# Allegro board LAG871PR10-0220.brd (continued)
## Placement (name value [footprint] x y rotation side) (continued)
CZ234  100P_0201_25V8J  [C_0201]  303.79 98.06 180 top
CZ303  0.1U_0201_10V6K  [C_0201]  146.41 50.26 180 top
CZ305  0.1U_0201_10V6K  [C_0201]  23.09 32.63 180 top
CZ306  470P_0402_50V7K  [C_0402]  23.29 33.9 180 top
CZ307  27P_0201_25V8  [C_0201]  303.76 95.87 270 top
CZ308  27P_0201_25V8  [C_0201]  303.79 98.63 180 top
CZ309  0.1U_0201_10V6K  [C_0201]  308.29 97.73 0 bottom
CZ311  27P_0402_50V8J  [C_0402]  269.33 63.91 90 top
CZ312  27P_0402_50V8J  [C_0402]  268.42 63.91 90 top
DA1  AZ5123-02S.R7G_SOT23-3  [L03ESDL5V0CC3-2_SOT23-3]  299.28 33.75 180 bottom
DA2  AZ5125-02S.R7G_SOT23-3  [AZ5125-02SPR7G_SOT23-3]  299.92 47.71 0 bottom
DA3  AZ5123-02S.R7G_SOT23-3  [L03ESDL5V0CC3-2_SOT23-3]  304.93 47.9 0 bottom
DA6  -  [L03ESDL5V0CG3-2_SOT-523-3]  302.33 20.06 180 bottom
DA7  -  [L03ESDL5V0CG3-2_SOT-523-3]  298.01 20.06 180 bottom
DA8  -  [RB751S-40_SOD523-2]  272.48 47.63 270 top
DC1  -  [RB751S-40_SOD523-2]  173.42 56.32 0 top
DC2  -  [RB751S-40_SOD523-2]  175.12 55.11 180 top
DC4  -  [RB521CM-30T2R_SOD923-2]  174.89 74.51 270 bottom
DD1  -  [CEST523NC5VB_SOT-523-3]  142.95 27.78 270 top
DE1  BZV55-B5V6_SOD80C2  [BZV55-B5V1_SOD80C2]  187.75 83.05 270 bottom
DE2  -  [RB751S-40_SOD523-2]  278.24 64.22 90 top
DI1  -  [AZ1045-04F_DFN2510P10E-10-9]  23.64 40.26 90 top
DI2  -  [CEST523NC5VB_SOT-523-3]  23.5 37.4 90 bottom
DI4  -  [AZ1045-04F_DFN2510P10E-10-9]  294.42 83.28 270 top
DI5  -  [CEST523NC5VB_SOT-523-3]  294.78 87.5 90 top
DT1  1N4148WS-L_SOD323-2  [1N4148WS-7-F_SOD323-2]  26 88.89 180 top
DT2  1N4148WS-L_SOD323-2  [1N4148WS-7-F_SOD323-2]  23.25 34.51 180 bottom
DT3  1N4148WS-L_SOD323-2  [1N4148WS-7-F_SOD323-2]  20.54 32.04 0 bottom
DT4  AZ4A24-01F.R7G_DFN0603P2Y2  [AZ4A24-01FPR7G_DFN0603P2Y2]  11.69 93.58 90 bottom
DT5  DESD3V3Z1BCSF-7 X2-DSN0603-2  [ESD8011MUT5G_X3DFN2-2]  13.91 81.81 270 bottom
DT6  DESD3V3Z1BCSF-7 X2-DSN0603-2  [ESD8011MUT5G_X3DFN2-2]  13.91 82.52 90 bottom
DT9  DESD3V3Z1BCSF-7 X2-DSN0603-2  [ESD8011MUT5G_X3DFN2-2]  13.15 89.72 90 bottom
DT10  DESD3V3Z1BCSF-7 X2-DSN0603-2  [ESD8011MUT5G_X3DFN2-2]  13.15 89.01 270 bottom
DT13  DESD3V3Z1BCSF-7 X2-DSN0603-2  [ESD8011MUT5G_X3DFN2-2]  13.91 81.81 270 top
DT14  DESD3V3Z1BCSF-7 X2-DSN0603-2  [ESD8011MUT5G_X3DFN2-2]  13.91 82.52 90 top
DT17  DESD3V3Z1BCSF-7 X2-DSN0603-2  [ESD8011MUT5G_X3DFN2-2]  13.15 89.72 90 top
DT18  DESD3V3Z1BCSF-7 X2-DSN0603-2  [ESD8011MUT5G_X3DFN2-2]  13.15 89.01 270 top
DT39  AZ1045-04F_DFN2510P10E-10-9  [L05ESDL5V0NA-4_SLP2510P8-10-9]  13.2 86.89 90 bottom
DT40  AZ1045-04F_DFN2510P10E-10-9  [L05ESDL5V0NA-4_SLP2510P8-10-9]  13.2 84.89 270 top
DV1  -  [BAT54CW_SOT323-3]  68.55 105.15 90 top
DV2  -  [BAT54CW_SOT323-3]  48.14 106.74 270 top
DV3  BAT54CTB_SOT-523  [BAT54CT-7-F_SOT523-3]  103.32 95.24 270 bottom
DV11  -  [RB751S-40_SOD523-2]  69.65 102.69 270 top
DV12  -  [RB751S-40_SOD523-2]  87.66 104.58 180 top
DV13  -  [CEST523NC5VB_SOT-523-3]  57.79 107.37 180 top
DV14  -  [CEST523NC5VB_SOT-523-3]  61.6 107.37 180 top
DZ1  -  [RB751S-40_SOD523-2]  273.65 50.92 180 top
DZ2  -  [RB751S-40_SOD523-2]  273.65 49.59 180 top
DZ5  -  [RB751S-40_SOD523-2]  273.01 60.35 90 top
DZ6  -  [RB751S-40_SOD523-2]  274.28 60.35 90 top
DZ8  -  [RB751S-40_SOD523-2]  277.95 30.18 270 bottom
DZ9  BAT54CTB_SOT-523-3  [BAT54CT-7-F_SOT523-3]  253.2 39.08 90 bottom
DZ10  -  [CEST523NC5VB_SOT-523-3]  91.89 107.94 180 top
DZ11  -  [CEST523NC5VB_SOT-523-3]  314.18 95.53 0 bottom
DZ12  -  [RB751S-40_SOD523-2]  300.69 6.14 90 top
DZ13  -  [AZ1045-04F_DFN2510P10E-10-9]  296.18 55.5 90 top
DZ14  -  [AZ1045-04F_DFN2510P10E-10-9]  310.69 96.66 0 bottom
DZ15  -  [AZ1045-04F_DFN2510P10E-10-9]  307.59 96.67 0 bottom
DZ21  -  [CEST523NC5VB_SOT-523-3]  96.84 107.94 180 top
FD1  FIDUCIAL MARK~D  [FIDUCIAL_C40M80]  10.42 20.31 0 top
FD2  FIDUCIAL MARK~D  [FIDUCIAL_C40M80]  268.64 107.74 0 top
FD3  FIDUCIAL MARK~D  [FIDUCIAL_C40M80]  10.55 20.06 180 bottom
FD4  FIDUCIAL MARK~D  [FIDUCIAL_C40M80]  270.27 104.71 180 bottom
FV1  1A_65V_T0603FF1000TM  [F_T0603FF1000TM]  91.21 101.21 180 bottom
FV2  0.5A_65V_T0603FF0500TM  [F_T0603FF0500TM]  77.31 110.04 0 top
FZ1  0.5A_65V_T0603FF0500TM  [F_T0603FF0500TM]  54.51 107.18 90 top
FZ2  1A_65V_T0603FF1000TM  [F_T0603FF1000TM]  104.3 106.47 90 top
H1  -  [H_3P7]  163.83 90.45 180 bottom
H2  -  [H_3P7]  163.83 69.25 180 bottom
H3  -  [H_3P7]  99.43 69.25 180 bottom
H4  -  [H_3P7]  99.43 90.45 180 bottom
H5  H_4P0  [H_4P0-G]  158.73 101.57 180 bottom
H8  H_4P0  [H_4P0-G]  158.73 25.15 180 bottom
H11  H_2P6  [H_2P6-G]  5.73 94.3 180 bottom
H12  H_2P6  [H_2P6-G]  4.43 77.85 180 bottom
H13  H_3P1  [H_3P1-G]  4.78 23.65 180 bottom
H14  H_2P3  [H_2P3-G]  49.23 111.95 180 bottom
H15  H_2P6  [H_2P6-G]  264.73 111.55 180 bottom
H16  H_2P6  [H_2P6-G]  301.59 102.45 180 bottom
H17  H_2P6  [H_2P6-G]  313.5 70.85 180 bottom
H18  H_3P1  [H_3P1-G]  312.68 23.65 180 bottom
H20  -  [H_3P2]  290.58 45.13 180 bottom
H21  -  [H_3P2]  276.44 102.35 180 bottom
H27  H_3P6X2P6  [H_3P6X2P6-G]  4.78 28.95 180 bottom
H28  H_2P6  [H_2P6-G]  312.68 28.95 180 bottom
H29  -  [H_0P6X2P8]  304.94 102.45 0 top
H30  -  [H_2P5X0P7]  8.39 94.3 90 top
H31  -  [H_2P5X0P7]  7.08 77.85 90 top
JANT1  I-PEX_20854-005E-00  [I-PEX_20854-005E-00_5P-T]  306.02 107.95 270 bottom
JANT2  I-PEX_20854-005E-00  [I-PEX_20854-005E-00_5P-T]  306.02 98.35 270 bottom
JAPS1  CVILU_CF4218FH0R0-05-NH  [CVILU_CF4218FH0R0-05-NH_18P-T]  298.45 31.03 180 bottom
JASA1  CVILU_CI1804M1HRG-NH  [CVILU_CI1804M1HRG-NH_4P]  106.93 112.05 180 bottom
JDEG1  JXT_FP241AH-010GAAM  [JXT_FP241AH-010GAAM_10P]  295.86 87.59 90 bottom
JDIMM1  LOTES_ADDR0206-P001A  [FOX_ASAA821-H4RB5-7H_260P]  57.46 39.23 180 bottom
JDIMM2  LOTES_ADDR0206-P001A  [FOX_ASAA821-H4RB5-7H_260P]  134.66 39.23 180 bottom
JEDP1  I-PEX_20879-040E-01  [I-PEX_20879-040E-01_40P-T]  57.43 111.32 180 bottom
JESPI  JXT_FP241AH-010GAAM  [JXT_FP241AH-010GAAM_10P]  295.92 78.63 90 bottom
JFAN1  ACES_50271-0040N-001  [ACES_50271-0040N-001_4P]  191.31 79.4 270 bottom
JFPBTN1  FOX_QT510166-L010-7H  [FOX_QT510166-L010-7H_16P]  307.8 100.8 270 bottom
JHDMI1  ACON_HMRBL-A41L0F  [ACON_HMRBL-A41L0F_19P-T]  11.6 60.25 90 bottom
JHP1  SINGA_2SJ3095-085111F  [SINGA_2SJ3095-085111F_6P]  304.51 42.95 90 bottom
JIRTS1  ACES_50208-0180N-P01  [ACES_50208-0180N-P01_18P-T-S]  88.32 112.05 180 bottom
JKBTP1  HRS_TF31-20S-0P5SH-800  [HRS_TF31-20S-0P5SH-800_20P-T]  245.08 32.55 0 bottom
JLED1  HRS_TF31-4S-0P5SH-800  [HRS_TF31-4S-0P5SH-800_4P-T]  309.08 6.95 0 bottom
JNGFF1  LOTES_APCI0128-P005A  [LOTES_APCI0128-P005A_75P]  257.05 54.38 270 bottom
JNGFF2  DEREN_40-42313-06711RHFAN  [ACES_40-42313-06711RHFAN_75P-T]  267.18 56.82 0 bottom
JNGFF3  LOTES_APCI0170-P001A  [LOTES_APCI0170-P001A_75P]  33.88 22.6 180 bottom
JRTC1  ACES_50271-0020N-001  [ACES_50271-0020N-001_2P]  290.34 15.26 270 bottom
JSD1  T-SOL_158-1240902600  [T-SOL_158-1240902600_23P-T]  302.95 61.03 90 top
JSIM1  TAISO_159-1000300600  [TAISO_159-1000300600_8P-T]  301.47 63.01 270 bottom
JSPI1  ACES_50506-02041-P01  [ACES_50506-02041-P01_20P]  184.6 72.01 180 bottom
JSPK1  ACES_50278-00801-001  [ACES_50278-00801-001_8P]  292.64 8.1 180 bottom
JTAG1  @SHORT PADS~D  [SHORTPADS]  273.56 96.26 180 top
JUSB1  ACON_TCRA2-9U1U93  [ACON_TCRA2-9U1U93_9P-T]  301.11 79.73 270 bottom
JUSB2  ACON_TCRA2-9U1U93  [ACON_TCRA2-9U1U93_9P-T]  16.36 45.25 90 bottom
JUSBC1  JAE_DX07SD24JJ2R1300~D  [JAE_DX07SD24JJ2R1300_24P]  7.55 88.47 270 top
JUSH1  HRS_TF31C-26S-0P5SH-800  [HRS_TF31C-26S-0P5SH-800_26P-T]  261.43 32.55 0 bottom
JXDP1  JXT_FP270H-061G1AM  [JXT_FP270H-061G1AM_61P]  73.88 96.5 180 bottom
LA5  BLM15PX600SN1D_2P  [MURAT_BLM15PX600SN1D_2P]  283.28 47.38 90 top
LA6  BLM15PD800SN1D_2P  [MURAT_BLM15PD800SN1D_2P]  303.87 20.47 270 bottom
LA7  BLM15PD800SN1D_2P  [MURAT_BLM15PD800SN1D_2P]  300.81 20.61 270 bottom
LA8  BLM15PD800SN1D_2P  [MURAT_BLM15PD800SN1D_2P]  299.54 20.36 270 bottom
LA9  BLM15PD800SN1D_2P  [MURAT_BLM15PD800SN1D_2P]  296.51 20.6 270 bottom
LA10  BLM15PX330SN1D_2P  [MURAT_BLM15PX330SN1D_2P]  299.36 45.52 0 top
LA11  BLM15PX330SN1D_2P  [MURAT_BLM15PX330SN1D_2P]  304.7 46.22 0 top
LA12  BLM15PX600SN1D_2P  [MURAT_BLM15PX600SN1D_2P]  278.39 34.85 270 top
LA13  HCB2012KF-121T50_2P  [TAI-T_HCB2012KF-121T50_2P]  276.8 49.05 90 top
LA14  BLM15PX600SN1D_2P  [MURAT_BLM15PX600SN1D_2P]  274.81 43.24 180 top
LA15  BLM15PX330SN1D_2P  [MURAT_BLM15PX330SN1D_2P]  297.31 38.26 270 top
LA16  BLM15PX330SN1D_2P  [MURAT_BLM15PX330SN1D_2P]  297.31 35.64 90 top
LC1  LQM18PN2R2NC0L_2P~D  [MURAT_BLM18EG221SN1D_2P]  146.72 103.73 180 top
LC2  LQM18PN2R2NC0L_2P~D  [MURAT_BLM18EG221SN1D_2P]  165.36 95.71 270 bottom
LC3  LQM18PN2R2NC0L_2P~D  [MURAT_BLM18EG221SN1D_2P]  148.93 95.74 180 top
LC4  BLM18EG221TN1D_2P~D  [MURAT_BLM18EG221SN1D_2P]  167.77 79.52 270 top
LC5  BLM15BD121SN1D_2P~D  [MURAT_BLM15BD121SN1D_2P]  153.44 97.09 0 top
LED3  LTW-C193DC-C_WHITE  [LED_LTW-C193DC-C_2P]  309.71 106.64 0 top
LI3  DLM0NSN900HY2D_4P  [MURAT_DLM0NSN900HY2D_4P]  24.82 36.38 180 bottom
LI7  DLM0NSN900HY2D_4P  [MURAT_DLM0NSN900HY2D_4P]  293.46 86.16 0 top
LI8  MCM1012B900F06BP_4P  [INPAQ_MCM1012B900F06BP_4P]  271.17 53.08 90 top
LI9  MCM1012B900F06BP_4P  [INPAQ_MCM1012B900F06BP_4P]  253.37 50.28 45 bottom
LI16  HCM1012GH900BP_4P  [INPAQ_HCM1012GH900BP_4P]  273.71 53.08 90 top
LI17  HCM1012GH900BP_4P  [INPAQ_HCM1012GH900BP_4P]  275.87 53.08 90 top
LT1  0.6UH_MND-04ABIR60M-XGL_20%  [MAG_MND-04ABIR60M-XGL_2P]  19.83 92.11 180 bottom
LT2  1UH_LQM18PN1R0MFHD_20%  [CHILI_PBY160808T-300Y-N_2P]  36.25 78.21 90 top
LV1  BLM15PX221SN1D_2P  [MURAT_BLM15PX221SN1D_2P]  67.32 108.62 270 top
LV3  HCM1012GH900BP_4P  [TAIYO_MCF12102G900-T_4P-NPM]  17.58 53.83 180 bottom
LV6  HCM1012GH900BP_4P  [TAIYO_MCF12102G900-T_4P-NPM]  17.55 57.56 180 bottom
LV9  HCM1012GH900BP_4P  [TAIYO_MCF12102G900-T_4P-NPM]  17.57 55.78 180 bottom
LV12  HCM1012GH900BP_4P  [TAIYO_MCF12102G900-T_4P-NPM]  17.6 59.49 180 bottom
LZ1  DLM0NSN900HY2D_4P  [MURAT_DLM0NSN900HY2D_4P]  60.14 106.25 90 top
NOREF  -  []  264.73 111.55 0 top
NOREF#2  -  []  312.68 28.95 0 top
NOREF#3  -  []  158.73 101.57 0 top
NOREF#4  -  []  5.73 94.3 0 top
NOREF#5  -  []  313.5 70.85 270 top
NOREF#6  -  []  109.99 52.44 0 top
NOREF#7  -  []  4.78 23.65 0 top
NOREF#8  -  []  312.68 28.95 0 top
NOREF#9  -  []  99.43 69.25 0 top
NOREF#10  -  []  90.94 51.62 180 top
NOREF#11  -  []  140.72 42.03 0 top
NOREF#12  -  []  301.59 102.45 0 top
NOREF#13  -  []  -18.83 173.46 0 top
NOREF#14  -  []  49.23 111.95 0 top
NOREF#15  -  []  305.73 9.65 0 top
NOREF#16  -  []  276.44 102.35 0 top
NOREF#17  -  []  158.73 25.15 180 top
NOREF#18  -  []  264.73 111.55 0 top
NOREF#19  -  []  37.15 35.3 0 top
NOREF#20  -  []  312.68 23.65 0 top
NOREF#21  -  []  163.83 69.25 0 top
NOREF#22  -  []  185.36 55.81 0 top
NOREF#23  -  []  290.58 45.13 0 top
NOREF#24  -  []  68.52 169.03 0 top
NOREF#25  -  []  170.9 -11.45 0 top
NOREF#26  -  []  128.66 49.78 0 top
NOREF#27  -  []  99.43 90.45 0 top
NOREF#28  -  []  163.83 90.45 0 top
NOREF#29  -  []  7.08 77.85 90 top
NOREF#30  -  []  8.39 94.3 90 top
NOREF#31  -  []  4.43 77.85 180 top
NOREF#32  -  []  4.78 28.95 0 top
NOREF#33  -  []  275.89 77.73 180 bottom
NOREF#34  -  []  127.45 57.33 180 bottom
NOREF#35  -  []  220.19 -2.53 180 bottom
NOREF#36  -  []  223.59 44.13 180 bottom
PBATT1  DEREN_40-42251-01001RHF  [DEREN_40-42251-01001RHF_10P-T]  236.98 35.12 180 bottom
PC1  2200P_0402_50V7K  [C_0402]  239.27 35.86 0 bottom
PC2  27P_0402_50V8J  [C_0402]  240 37.99 0 bottom
PC3  1U_0402_25V6K  [C_0402]  239.46 31.62 270 top
PC4  0.022U_0402_25V7K  [C_0402]  50.32 91.93 90 bottom
PC5  1000P_0402_50V7K  [C_0402]  48.14 92.98 270 bottom
PC6  0.022U_0402_25V7K  [C_0402]  58.31 92.11 0 bottom
PC7  0.1U_0402_25V6  [C_0402]  58.83 91.75 90 top
PC8  10U_0603_25V6M  [C_0603]  55.09 85.48 90 bottom
PC10  4.7U_0402_6.3V6M  [C_0402]  66.77 94.66 180 bottom
PC11  1000P_0402_50V7K  [C_0402]  62.85 94.66 0 bottom
PC12  82P_0402_50V8J  [C_0402]  65.67 94.27 90 top
PC13  0.1U_0402_10V7K  [C_0402]  55.46 94.71 180 top
PC100  0.1U_0402_25V6  [C_0402]  193 101.54 90 bottom
PC101  27P_0201_25V8  [C_0201]  189.11 100.11 180 top
PC102  0.1U_0402_25V6  [C_0402]  194.23 100.47 0 top
PC103  2200P_0402_50V7K  [C_0402]  186.53 100.23 270 top
PC104  10U_0603_25V6M  [C_0603]  187.62 100.17 270 bottom
PC105  10U_0603_25V6M  [C_0603]  187.62 100.15 270 top
PC106  22U_0603_6.3V6M  [C_0603]  190.25 88.33 0 bottom
PC107  22U_0603_6.3V6M  [C_0603]  189.1 87.13 0 bottom
PC108  22U_0603_6.3V6M  [C_0603]  189.1 85.92 0 bottom
PC109  22U_0603_6.3V6M  [C_0603]  189.07 87.14 0 top
PC110  22U_0603_6.3V6M  [C_0603]  190.25 88.39 0 top
PC111  4.7U_0402_6.3V6M  [C_0402]  193.6 96.78 270 top
PC112  680P_0402_50V7K  [C_0402]  195.11 90.76 270 top
PC113  1000P_0402_50V7K  [C_0402]  190.67 94.52 0 top
PC114  0.1U_0402_25V6  [C_0402]  42.07 24.43 90 top
PC115  0.1U_0402_25V6  [C_0402]  47.22 21.94 180 top
PC116  2200P_0402_50V7K  [C_0402]  47.22 22.86 180 top
PC117  10U_0603_25V6M  [C_0603]  47.47 24.49 90 bottom
PC118  10U_0603_25V6M  [C_0603]  47.47 24.49 90 top
PC119  2.2U_0402_6.3V6M  [C_0402]  41.61 29.04 180 top
PC120  22U_0603_6.3V6M  [C_0603]  36.76 22.52 180 top
PC121  22U_0603_6.3V6M  [C_0603]  36.76 23.73 180 top
PC122  22U_0603_6.3V6M  [C_0603]  40.61 23.36 0 top
PC123  22U_0603_6.3V6M  [C_0603]  40.61 23.36 0 bottom
PC124  22U_0603_6.3V6M  [C_0603]  38.26 23.35 0 top
PC125  680P_0402_50V7K  [C_0402]  44.66 20.59 180 top
PC126  4.7U_0402_6.3V6M  [C_0402]  42.86 31.17 90 top
PC127  1000P_0402_50V7K  [C_0402]  44.05 31.48 90 top
PC128  4.7U_0402_6.3V6M  [C_0402]  186.54 93.91 270 top
PC129  22U_0603_6.3V6M  [C_0603]  189.1 85.92 0 top
PC130  22U_0603_6.3V6M  [C_0603]  38.26 23.35 0 bottom
PC131  82P_0402_50V8J  [C_0402]  186.53 100.23 270 bottom
PC132  82P_0402_50V8J  [C_0402]  44.32 24.29 270 top
PC133  100P_0402_50V8J  [C_0402]  194.85 101.56 90 bottom
PC134  100P_0402_50V8J  [C_0402]  193.94 101.54 90 bottom
PC135  100P_0402_50V8J  [C_0402]  189.79 82.44 0 top
PC136  27P_0402_50V8J  [C_0402]  189.79 83.38 0 top
PC137  100P_0402_50V8J  [C_0402]  39.11 17.44 270 top
PC138  100P_0402_50V8J  [C_0402]  38.21 17.44 270 top
PC139  100P_0402_50V8J  [C_0402]  47.22 22.86 180 bottom
PC140  100P_0402_50V8J  [C_0402]  47.22 21.94 180 bottom
PC141  27P_0201_25V8  [C_0201]  48.47 25.2 90 top
PC142  27P_0201_25V8  [C_0201]  40.73 24.3 0 top
PC161  22U_0603_6.3V6M  [C_0603]  189.1 84.71 0 bottom
PC162  22U_0603_6.3V6M  [C_0603]  189.12 84.71 0 top
PC163  22U_0603_6.3V6M  [C_0603]  41.6 22.12 0 top
PC164  22U_0603_6.3V6M  [C_0603]  36.76 24.97 180 top
PC200  10U_0603_25V6M  [C_0603]  219.05 27.02 270 top
PC201  10U_0603_25V6M  [C_0603]  219.05 27.02 270 bottom
PC202  82P_0402_50V8J  [C_0402]  217.06 26.74 270 bottom
PC203  0.1U_0402_25V6  [C_0402]  217.96 26.74 270 bottom
PC204  680P_0402_50V7K  [C_0402]  210.89 36.63 270 top
PC205  0.1U_0402_25V6  [C_0402]  217.3 30.03 180 top
PC206  1U_0201_6.3V6M  [C_0201]  218.87 30.28 180 top
PC207  2.2U_0402_6.3V6M  [C_0402]  218.76 29.53 270 top
PC208  330P_0402_50V7K  [C_0402]  216.15 27.93 0 top
PC209  22U_0603_6.3V6M  [C_0603]  223.65 32 90 top
PC210  22U_0603_6.3V6M  [C_0603]  211.26 32.84 90 top
PC211  22U_0603_6.3V6M  [C_0603]  211.26 32.84 90 bottom
PC212  22U_0603_6.3V6M  [C_0603]  209.98 32.87 90 top
PC213  22U_0603_6.3V6M  [C_0603]  209.98 32.87 90 bottom
PC214  10U_0603_10V6M  [C_0603]  208.71 32.85 90 top
PC216  2200P_0402_50V7K  [C_0402]  213.29 32.51 90 bottom
PC217  100P_0402_50V8J  [C_0402]  207.59 32.81 90 bottom
PC218  1U_0201_6.3V6M  [C_0201]  224.73 27.87 0 top
PC219  22U_0603_6.3V6M  [C_0603]  225.05 30.03 270 top
PC221  0.1U_0402_10V7K  [C_0402]  224.99 26.36 270 top
PC222  0.1U_0402_10V7K  [C_0402]  226.5 26.79 0 top
PC223  10U_0603_10V6M  [C_0603]  208.71 32.85 90 bottom
PC224  100P_0402_50V8J  [C_0402]  206.64 32.81 90 bottom
PC225  100P_0402_50V8J  [C_0402]  212.35 32.51 90 bottom
PC226  1U_0201_6.3V6M  [C_0201]  218.87 30.85 180 top
PC227  1U_0201_6.3V6M  [C_0201]  225.1 27.3 0 top
PC228  27P_0201_25V8  [C_0201]  214.06 32.67 90 bottom
PC230  27P_0201_25V8  [C_0201]  220.33 25.98 270 top
PC231  100P_0201_25V8J  [C_0201]  220.92 25.98 270 top
PC301  82P_0201_50V8J  [C_0201]  185.82 104.38 0 top
PC302  680P_0402_50V7K  [C_0402]  192.2 112.62 270 top
PC303  100P_0402_50V8J  [C_0402]  187.57 105.7 270 top
PC304  0.1U_0402_25V6  [C_0402]  186.85 109.14 90 top
PC305  10U_0603_25V6M  [C_0603]  188.63 106.2 270 top
PC306  10U_0603_25V6M  [C_0603]  188.63 106.2 270 bottom
PC307  330P_0402_50V7K  [C_0402]  196.09 111.32 270 top
PC308  22U_0603_6.3V6M  [C_0603]  177.93 110.97 90 bottom
PC309  22U_0603_6.3V6M  [C_0603]  176.72 110.97 90 bottom
PC310  22U_0603_6.3V6M  [C_0603]  176.72 110.97 90 top
PC311  22U_0603_6.3V6M  [C_0603]  177.94 110.97 90 top
PC312  1U_0201_6.3V6M  [C_0201]  194.63 111.79 270 top
PC313  2.2U_0402_6.3V6M  [C_0402]  193.01 110.89 0 top
PC314  1U_0201_6.3V6M  [C_0201]  195.21 111.79 270 top
PC315  100P_0402_50V8J  [C_0402]  175.64 110.9 90 bottom
PC316  100P_0402_50V8J  [C_0402]  175.63 110.9 90 top
PC317  27P_0201_25V8  [C_0201]  187.31 106.12 180 bottom
PC318  82P_0201_50V8J  [C_0201]  187.31 105.54 180 bottom
PC350  0.022U_0402_25V7K  [C_0402]  194.58 106.71 0 bottom
PC360  0.1U_0402_25V6  [C_0402]  194.82 105.8 0 bottom
PC401  470P_0402_50V7K  [C_0402]  78.43 24.25 180 top
PC402  0.1U_0402_25V6  [C_0402]  81.73 30.97 90 top
PC403  10U_0603_10V6M  [C_0603]  89.16 28.25 90 top
PC404  10U_0603_10V6M  [C_0603]  87.94 28.25 90 top
PC405  47P_0402_50V8J  [C_0402]  88.72 27.31 270 top
PC406  22U_0603_6.3V6M  [C_0603]  76.47 25.22 270 top
PC407  22U_0603_6.3V6M  [C_0603]  75.25 25.22 270 top
PC408  0.1U_0402_25V6  [C_0402]  89.7 27.29 270 top
PC409  100P_0402_50V8J  [C_0402]  87.76 27.31 270 top
PC411  0.1U_0402_25V6  [C_0402]  174.61 24.69 270 top
PC412  10U_0603_10V6M  [C_0603]  180.55 27.13 270 top
PC413  10U_0603_10V6M  [C_0603]  179.34 27.13 270 top
PC414  100P_0402_50V8J  [C_0402]  178.25 27.44 90 top
PC415  22U_0603_6.3V6M  [C_0603]  191.32 25.25 270 top
PC416  47P_0402_50V8J  [C_0402]  177.33 27.46 90 top
PC417  0.1U_0402_25V6  [C_0402]  178.25 26.56 270 top
PC418  2200P_0402_50V7K  [C_0402]  177.32 26.58 270 top
PC419  680P_0402_50V7K  [C_0402]  188.07 23.91 0 top
PC424  22U_0603_6.3V6M  [C_0603]  190.11 25.25 270 top
PC425  10U_0402_6.3V6M  [C_0402]  74.19 24.66 270 top
PC426  10U_0402_6.3V6M  [C_0402]  73.28 24.66 270 top
PC427  10U_0402_6.3V6M  [C_0402]  189.01 29.08 90 top
PC428  10U_0402_6.3V6M  [C_0402]  189.92 29.08 90 top
PC501  22U_0603_6.3V6M  [C_0603]  174.5 103.12 90 bottom
PC503  68P_0402_50V8J  [C_0402]  180.14 102.26 90 bottom
PC504  22U_0603_6.3V6M  [C_0603]  174.51 103.13 90 top
PC505  .1U_0402_16V7K  [C_0402]  177.93 105.16 90 top
PC506  680P_0402_50V7K  [C_0402]  175.05 106.82 180 bottom
PC513  .1U_0402_16V7K  [C_0402]  125.37 25.26 270 top
PC514  4.7U_0402_6.3V6M  [C_0402]  122.96 27.74 180 top
PC515  0.01UF_0402_25V7K  [C_0402]  118.94 26.87 270 top
PC516  22U_0603_6.3V6M  [C_0603]  118.99 28.05 0 top
PC517  4.7U_0402_6.3V6M  [C_0402]  122.96 28.64 180 top
PC530  22U_0603_6.3V6M  [C_0603]  185.74 106.04 180 bottom
PC601  680P_0402_50V7K  [C_0402]  68.41 67.47 0 top
PC602  0.1U_0402_25V6  [C_0402]  57.13 58.07 270 top
PC603  4.7U_0402_6.3V6M  [C_0402]  59.14 61.97 180 top
PC604  1U_0402_25V6K  [C_0402]  59.08 63.1 180 top
PC605  47P_0402_50V8J  [C_0402]  57.04 56.11 0 top
PC606  100U_D_20VM_R55M  [C_D]  69.68 87.29 90 bottom
PC607  100U_D_20VM_R55M  [C_D]  71.74 83.09 270 bottom
PC608  10U_0603_25V6M  [C_0603-S3]  99.87 96.63 270 bottom
PC609  27P_0201_25V8  [C_0201]  98.42 96.63 270 top
PC610  82P_0201_50V8J  [C_0201]  98.99 96.63 270 top
PC611  0.22U_0402_25V6K  [C_0402]  94.16 97.61 180 top
PC612  10U_0603_25V6M  [C_0603-S3]  99.89 96.63 270 top
PC613  330P_0402_50V7K  [C_0402]  61.58 53.79 90 top
PC614  2200P_0402_50V7K  [C_0402]  64.24 52.88 180 top
PC616  68P_0402_50V8J  [C_0402]  64.17 53.77 90 top
PC617  1200P_0402_50V7K  [C_0402]  67.75 51.82 180 top
PC618  330P_0402_50V7K  [C_0402]  67.82 49.87 90 top
PC619  0.01UF_0402_25V7K  [C_0402]  68.72 52.74 90 top
PC620  0.082U_0402_16V7K  [C_0402]  66.87 53.59 0 top
PC621  820P_0402_25V7  [C_0402]  65.15 51.78 90 top
PC622  680P_0402_50V7K  [C_0402]  92.49 89.52 180 top
PC624  0.022U_0402_16V7K  [C_0402]  70.19 51.59 0 top
PC625  330P_0402_50V7K  [C_0402]  74.19 55.29 180 top
PC626  0.1U_0402_25V6  [C_0402]  69.58 53.61 0 top
PC627  2200P_0402_50V7K  [C_0402]  73.81 51.66 270 top
PC628  33P_0402_50V8J  [C_0402]  69.37 65.63 90 top
PC629  2200P_0402_50V7K  [C_0402]  75.48 57.08 90 top
PC630  2200P_0402_50V7K  [C_0402]  73.39 65.47 90 top
PC631  4700P_0402_25V7K  [C_0402]  71.52 67.42 0 top
PC632  1000P_0402_50V7K  [C_0402]  62 65.97 90 top
PC633  4700P_0402_25V7K  [C_0402]  63.43 70.58 270 top
PC635  0.022U_0402_16V7K  [C_0402]  72.38 52.65 90 top
PC636  33P_0402_50V8J  [C_0402]  74.22 57.02 180 top
PC637  0.033U_0402_25V7K  [C_0402]  64.36 70.57 270 top
PC638  0.022U_0402_16V7K  [C_0402]  74.2 53.56 180 top
PC639  1500P_0402_50V7K  [C_0402]  75.93 60.78 180 top
PC640  2200P_0402_50V7K  [C_0402]  67.5 67.51 180 top
PC641  .1U_0402_16V7K  [C_0402]  72 50.79 0 top
PC642  0.068U_0402_16V7K  [C_0402]  73.32 63.66 90 top
PC643  330P_0402_50V7K  [C_0402]  71.53 65.63 0 top
PC644  .1U_0402_16V7K  [C_0402]  62.99 68.64 0 top
PC645  .1U_0402_16V7K  [C_0402]  76.02 65.09 270 top
PC646  2200P_0402_25V7K  [C_0402]  75.08 63.66 90 top
PC647  680P_0402_50V7K  [C_0402]  75.01 59.87 0 top
PC649  0.01UF_0402_25V7K  [C_0402]  64.76 65.73 90 top
PC650  0.082U_0402_16V7K  [C_0402]  65.67 65.73 90 top
PC651  330P_0402_50V7K  [C_0402]  75.04 62.58 270 top
PC652  330P_0402_50V7K  [C_0402]  65.66 67.51 180 top
PC653  0.082U_0402_16V7K  [C_0402]  74.14 61.66 180 top
PC654  0.01UF_0402_25V7K  [C_0402]  74.18 62.57 180 top
PC655  0.22U_0402_25V6K  [C_0402]  75.04 85.01 90 bottom
PC656  10U_0603_25V6M  [C_0603-S3]  72.63 89.91 90 top
PC657  10U_0603_25V6M  [C_0603-S3]  72.65 88.95 270 bottom
PC658  10U_0603_25V6M  [C_0603-S3]  72.66 88.96 270 top
PC659  0.1U_0402_25V6  [C_0402]  73.7 89.19 90 top
PC660  2200P_0402_50V7K  [C_0402]  78.1 82.8 0 top
PC661  4.7U_0402_6.3V6M  [C_0402]  81.04 89.21 90 bottom
PC662  680P_0402_50V7K  [C_0402]  78.75 93.79 270 top
PC663  0.22U_0402_25V6K  [C_0402]  71.11 71.59 0 bottom
PC664  10U_0603_25V6M  [C_0603-S3]  73.03 73.72 180 bottom
PC665  10U_0603_25V6M  [C_0603-S3]  73.03 73.72 180 top
PC666  0.1U_0402_25V6  [C_0402]  75.63 73.53 0 top
PC667  2200P_0402_50V7K  [C_0402]  75.52 72.61 0 top
PC668  4.7U_0402_6.3V6M  [C_0402]  75.55 66.21 0 bottom
PC669  4.7U_0402_6.3V6M  [C_0402]  72.51 68.42 90 bottom
PC670  680P_0402_50V7K  [C_0402]  83.89 72.76 180 top
PC671  0.22U_0402_25V6K  [C_0402]  74.62 80.89 0 bottom
PC672  10U_0603_25V6M  [C_0603-S3]  77.58 83.85 0 bottom
PC673  10U_0603_25V6M  [C_0603-S3]  77.6 83.86 0 top
PC674  10U_0603_25V6M  [C_0603-S3]  74.16 73.54 90 bottom
PC675  10U_0603_25V6M  [C_0603-S3]  74.16 73.53 90 top
PC676  4.7U_0402_6.3V6M  [C_0402]  78.21 86.35 180 bottom
PC677  4.7U_0402_6.3V6M  [C_0402]  75.95 77.71 90 bottom
PC678  680P_0402_50V7K  [C_0402]  84.17 81.49 180 top
PC682  10U_0603_25V6M  [C_0603-S3]  72.64 89.91 90 bottom
PC683  10U_0603_25V6M  [C_0603-S3]  76.03 83.13 180 bottom
PC684  10U_0603_25V6M  [C_0603-S3]  76.03 83.13 180 top
PC685  4.7U_0402_6.3V6M  [C_0402]  91.37 92.81 270 top
PC686  0.1U_0402_25V6  [C_0402]  73.7 89.19 90 bottom
PC687  0.1U_0402_25V6  [C_0402]  75.63 73.53 0 bottom
PC688  0.1U_0402_25V6  [C_0402]  78.1 82.8 0 bottom
PC689  27P_0201_25V8  [C_0201]  76.41 89.26 90 top
PC690  82P_0201_50V8J  [C_0201]  74.95 89.26 90 top
PC691  27P_0201_25V8  [C_0201]  72.62 72.19 180 top
PC692  82P_0201_50V8J  [C_0201]  72.62 72.78 180 top
PC697  4.7U_0402_6.3V6M  [C_0402]  79.69 75.46 0 bottom
PC700  0.1U_0402_25V6  [C_0402]  50.54 69.87 0 top
PC701  2200P_0402_50V7K  [C_0402]  50.56 68.55 0 top
PC702  10U_0805_25VAK  [C_0805]  49.43 74.03 180 bottom
PC703  10U_0805_25VAK  [C_0805]  49.43 72.27 180 bottom
PC704  10U_0805_25VAK  [C_0805]  50.09 64.98 0 bottom
PC705  10U_0603_25V6M  [C_0603]  50.53 65.72 0 top
PC706  15U_B2_25VM_R100M  [C_B2]  51.46 72.99 180 bottom
PC707  10U_0603_25V6M  [C_0603]  59.98 80.96 270 top
PC708  10U_0603_25V6M  [C_0603]  58.74 80.94 270 top
PC709  10U_0603_25V6M  [C_0603]  58.74 80.94 270 bottom
PC710  10U_0603_25V6M  [C_0603]  59.98 80.96 270 bottom
PC715  15U_B2_25VM_R100M  [C_B2]  67.72 81.75 90 bottom
PC719  4.7U_0402_6.3V6M  [C_0402]  46.13 57.94 0 bottom
PC720  0.1U_0402_25V6  [C_0402]  63.36 80.67 270 top
PC721  2200P_0402_50V7K  [C_0402]  64.67 80.67 270 top
PC722  0.1U_0201_25V6K  [C_0201]  65.93 80.63 270 top
PC723  1U_0402_25V6K  [C_0402]  62.05 80.68 270 top
PC725  1U_0402_25V6K  [C_0402]  45.17 57.96 90 bottom
PC726  1U_0402_25V6K  [C_0402]  47.04 58.87 180 bottom
PC727  0.47U_0402_25V6K  [C_0402]  45.41 58.77 180 top
PC728  0.1U_0201_25V6K  [C_0201]  60.86 80.58 270 top
PC729  0.1U_0201_25V6K  [C_0201]  68.25 82.54 270 top
PC730  0.1U_0201_25V6K  [C_0201]  57.79 80.21 270 top
PC731  82P_0201_50V8J  [C_0201]  66.74 80.72 270 top
PC732  82P_0201_50V8J  [C_0201]  68.87 82.54 270 top
PC733  82P_0201_50V8J  [C_0201]  58.46 83.65 135 top
PC734  2200P_0201_16V7K  [C_0201]  67.62 82.54 270 top
PC735  2200P_0201_16V7K  [C_0201]  59.65 84.32 135 top
PC736  0.1U_0402_25V6  [C_0402]  41.85 54.4 90 top
PC737  2.2U_0402_25V6M  [C_0402]  40.34 57.63 0 top
PC738  4.7U_0402_6.3V6M  [C_0402]  52.74 57.72 90 top
PC739  4.7U_0402_6.3V6M  [C_0402]  43.44 56.2 270 top
PC740  0.47U_0402_25V6K  [C_0402]  51.44 54.22 0 top
PC741  10U_0603_25V6M  [C_0603]  229.06 37.67 180 bottom
PC742  10U_0603_25V6M  [C_0603]  229.06 38.89 180 bottom
PC743  4700P_0402_25V7K  [C_0402]  229.18 42.98 0 bottom
PC744  10P_0402_50V8J  [C_0402]  42.11 49.22 270 top
PC745  0.1U_0402_25V6  [C_0402]  51.37 52.34 0 top
PC746  680P_0402_50V7K  [C_0402]  55.72 72.4 180 top
PC747  680P_0402_50V7K  [C_0402]  57.68 75.91 90 top
PC748  1U_0402_25V6K  [C_0402]  51.4 51.43 0 top
PC749  560P_0402_50V7K  [C_0402]  46.36 49.28 270 top
PC750  0.1U_0402_25V6  [C_0402]  48.03 49.27 270 top
PC751  0.01UF_0402_25V7K  [C_0402]  45.71 49.27 0 bottom
PC752  1U_0402_25V6K  [C_0402]  52.28 50.48 270 top
PC753  0.22U_0402_25V6K  [C_0402]  53.19 49.12 0 top
PC754  0.1U_0402_10V7K  [C_0402]  44.77 63.93 90 top
PC755  0.1U_0402_25V6  [C_0402]  51.09 47.68 90 top
PC756  22P_0201_25V8  [C_0201]  54.34 57.97 180 bottom
PC757  47P_0201_25V8J  [C_0201]  54.34 58.6 180 bottom
PC758  100P_0201_25V8J  [C_0201]  196.27 74.23 180 bottom
PC759  22P_0201_25V8  [C_0201]  223.01 39.26 270 bottom
PC760  47P_0201_25V8J  [C_0201]  223.64 39.26 270 bottom
PC761  100P_0201_25V8J  [C_0201]  196.27 74.84 180 bottom
PC800  100P_0402_50V8J  [C_0402]  44.86 74.55 0 top
PC801  0.01UF_0402_25V7K  [C_0402]  40.46 84.02 270 top
PC802  1500P_0402_50V7K  [C_0402]  49.28 77.38 270 bottom
PC803  0.47U_0402_25V6K  [C_0402]  44.02 85.92 0 bottom
PC804  220P_0402_50V7K  [C_0402]  46.86 73.72 0 top
PC805  1200P_0402_50V7K  [C_0402]  43.48 76.53 180 top
PC806  100P_0402_50V8J  [C_0402]  39.26 85.25 270 bottom
PC807  1000P_0402_50V7K  [C_0402]  38.3 85.25 270 bottom
PC808  0.1U_0402_25V6  [C_0402]  43.44 87.76 90 top
PC809  100P_0402_50V8J  [C_0402]  44.34 87.76 90 top
PC810  1500P_0402_50V7K  [C_0402]  33.86 101.51 270 top
PC811  10U_0402_6.3V6M  [C_0402]  48.55 81.13 0 top
PC812  100P_0402_50V8J  [C_0402]  43.33 79.5 180 top
PC813  2.2U_0402_25V6M  [C_0402]  43.3 83.84 90 top
PC814  0.1U_0402_10V7K  [C_0402]  44.38 90.67 0 top
PC865  0.1U_0402_25V6  [C_0402]  50.87 97.39 180 top
PC906  2200P_0402_50V7K  [C_0402]  42.94 42.98 180 bottom
PC1000  22U_0603_6.3V6M  [C_0603]  85.13 84.41 180 bottom
PC1001  22U_0603_6.3V6M  [C_0603]  85.13 84.41 180 top
PC1002  22U_0603_6.3V6M  [C_0603]  85.13 83.15 180 bottom
PC1003  22U_0603_6.3V6M  [C_0603]  85.13 83.15 180 top
PC1004  22U_0603_6.3V6M  [C_0603]  134.52 82.72 0 top
PC1005  22U_0603_6.3V6M  [C_0603]  130.69 79.1 0 top
PC1006  22U_0603_6.3V6M  [C_0603]  135.4 80.32 0 top
PC1007  22U_0603_6.3V6M  [C_0603]  130.7 80.3 0 top
PC1008  22U_0603_6.3V6M  [C_0603]  134.45 80.32 180 top
PC1009  22U_0603_6.3V6M  [C_0603]  134.44 79.1 180 top
PC1011  22U_0603_6.3V6M  [C_0603]  135.39 79.1 0 top
PC1012  22U_0603_6.3V6M  [C_0603]  135.41 81.52 0 top
PC1013  22U_0603_6.3V6M  [C_0603]  126.37 100.96 180 bottom
PC1014  22U_0603_6.3V6M  [C_0603]  126.37 100.96 180 top
PC1015  22U_0603_6.3V6M  [C_0603]  129.48 100.96 180 top
PC1016  22U_0603_6.3V6M  [C_0603]  129.48 100.96 180 bottom
PC1017  22U_0603_6.3V6M  [C_0603]  123.26 100.96 180 bottom
PC1018  22U_0603_6.3V6M  [C_0603]  123.26 100.96 180 top
PC1019  22U_0603_6.3V6M  [C_0603]  132.1 81.5 180 top
PC1020  22U_0603_6.3V6M  [C_0603]  132.25 82.7 180 top
PC1031  1U_0201_6.3V6M  [C_0201]  120.92 86.25 0 top
PC1032  1U_0201_6.3V6M  [C_0201]  120.89 85.64 0 top
PC1033  1U_0201_6.3V6M  [C_0201]  122.69 85.64 180 top
PC1034  1U_0201_6.3V6M  [C_0201]  122.71 86.24 180 top
PC1035  1U_0201_6.3V6M  [C_0201]  123.32 86.24 0 top
PC1036  1U_0201_6.3V6M  [C_0201]  123.33 85.64 0 top
PC1037  1U_0201_6.3V6M  [C_0201]  125.11 86.25 180 top
PC1038  1U_0201_6.3V6M  [C_0201]  125.12 85.66 180 top
PC1039  1U_0201_6.3V6M  [C_0201]  125.74 86.24 0 top
PC1040  1U_0201_6.3V6M  [C_0201]  125.74 85.66 0 top
PC1041  1U_0201_6.3V6M  [C_0201]  127.55 86.23 180 top
PC1042  1U_0201_6.3V6M  [C_0201]  127.55 85.63 180 top
PC1043  1U_0201_6.3V6M  [C_0201]  128.16 86.23 0 top
PC1044  1U_0201_6.3V6M  [C_0201]  128.17 85.62 0 top
PC1045  1U_0201_6.3V6M  [C_0201]  129.95 86.23 180 top
PC1046  1U_0201_6.3V6M  [C_0201]  129.95 85.62 180 top
PC1047  1U_0201_6.3V6M  [C_0201]  130.63 86.23 0 top
PC1048  1U_0201_6.3V6M  [C_0201]  130.63 85.62 0 top
PC1049  1U_0201_6.3V6M  [C_0201]  132.44 86.23 180 top
PC1050  1U_0201_6.3V6M  [C_0201]  132.44 85.62 180 top
PC1051  1U_0201_6.3V6M  [C_0201]  133.13 85.59 0 top
PC1052  1U_0201_6.3V6M  [C_0201]  133.12 86.2 0 top
PC1053  1U_0201_6.3V6M  [C_0201]  134.35 86.21 0 top
PC1054  1U_0201_6.3V6M  [C_0201]  134.35 85.57 0 top
PC1055  1U_0201_6.3V6M  [C_0201]  136.17 86.24 180 top
PC1056  1U_0201_6.3V6M  [C_0201]  136.17 85.58 180 top
PC1057  1U_0201_6.3V6M  [C_0201]  128.24 75.77 0 top
PC1058  1U_0201_6.3V6M  [C_0201]  128.24 75.1 0 top
PC1059  1U_0201_6.3V6M  [C_0201]  130.04 75.76 180 top
PC1060  1U_0201_6.3V6M  [C_0201]  130.04 75.1 180 top
PC1061  1U_0201_6.3V6M  [C_0201]  130.68 75.75 0 top
PC1062  1U_0201_6.3V6M  [C_0201]  130.68 75.09 0 top
PC1063  1U_0201_6.3V6M  [C_0201]  132.51 75.74 180 top
PC1064  1U_0201_6.3V6M  [C_0201]  132.5 75.08 180 top
PC1065  1U_0201_6.3V6M  [C_0201]  133.29 75.66 0 top
PC1066  1U_0201_6.3V6M  [C_0201]  133.25 75.03 0 top
PC1067  1U_0201_6.3V6M  [C_0201]  135.08 75.65 180 top
PC1068  1U_0201_6.3V6M  [C_0201]  135.08 75.04 180 top
PC1069  1U_0201_6.3V6M  [C_0201]  135.73 75.62 0 top
PC1070  1U_0201_6.3V6M  [C_0201]  135.73 75.05 0 top
PC1071  47U_0603_6.3V6M  [C_0603-S3]  128.71 83.9 0 top
PC1072  47U_0603_6.3V6M  [C_0603-S3]  130.37 77.91 0 top
PC1073  47U_0603_6.3V6M  [C_0603-S3]  122.83 83.85 180 top
PC1074  47U_0603_6.3V6M  [C_0603-S3]  123.85 83.85 0 top
PC1075  47U_0603_6.3V6M  [C_0603-S3]  132.49 83.9 180 top
PC1076  47U_0603_6.3V6M  [C_0603-S3]  127.6 83.84 180 top
PC1077  47U_0603_6.3V6M  [C_0603-S3]  134.18 83.92 0 top
PC1078  47U_0603_6.3V6M  [C_0603-S3]  134.15 77.83 180 top
PC1079  47U_0603_6.3V6M  [C_0603-S3]  129.29 77.93 180 top
PC1080  47U_0603_6.3V6M  [C_0603-S3]  135.37 77.9 0 top
PC1081  22U_0603_6.3V6M  [C_0603]  125.91 109.71 180 bottom
PC1082  22U_0603_6.3V6M  [C_0603]  125.91 109.71 180 top
PC1083  22U_0603_6.3V6M  [C_0603]  125.91 107.4 180 bottom
PC1084  22U_0603_6.3V6M  [C_0603]  128.04 109.71 0 top
PC1085  22U_0603_6.3V6M  [C_0603]  128.04 109.71 0 bottom
PC1086  22U_0603_6.3V6M  [C_0603]  128.08 107.4 0 top
PC1087  22U_0603_6.3V6M  [C_0603]  128.08 107.4 0 bottom
PC1088  22U_0603_6.3V6M  [C_0603]  125.91 107.4 180 top
PC1089  1U_0201_6.3V6M  [C_0201]  132.42 74.48 180 top
PC1090  1U_0201_6.3V6M  [C_0201]  129.47 82.94 0 top
PC1091  330U_D2_2.5VM_R9M  [C_D2]  132.21 103.93 0 bottom
PC1092  470U_D2_2VM_R4.5M  [C_D2]  127.87 103.93 180 bottom
PC1093  220U_D7_2VM_R4.5M  [C_D7]  128.56 80.88 180 top
PC1094  220U_D7_2VM_R4.5M  [C_D7]  128.35 104.39 180 top
PC1095  330U_D2_2.5VM_R9M  [C_D2]  132.21 108.78 0 bottom
PC1096  100P_0201_25V8J  [C_0201]  131.9 96.03 90 top
PC1097  100P_0201_25V8J  [C_0201]  84.49 82.25 180 top
PC1098  27P_0201_25V8  [C_0201]  84.25 85.29 180 top
PC1099  82P_0201_50V8J  [C_0201]  84.25 85.85 180 top
PC1101  22U_0603_6.3V6M  [C_0603]  89.99 69.53 270 bottom
PC1102  22U_0603_6.3V6M  [C_0603]  89.99 69.53 270 top
PC1103  22U_0603_6.3V6M  [C_0603]  91.52 70.12 270 bottom
PC1104  22U_0603_6.3V6M  [C_0603]  91.52 70.12 270 top
PC1105  22U_0603_6.3V6M  [C_0603]  90.02 73.88 180 top
PC1106  22U_0603_6.3V6M  [C_0603]  90.03 73.89 180 bottom
PC1107  22U_0603_6.3V6M  [C_0603]  94.65 81.97 90 top
PC1108  22U_0603_6.3V6M  [C_0603]  115.26 84 270 top
PC1109  22U_0603_6.3V6M  [C_0603]  118.94 83.88 0 top
PC1110  22U_0603_6.3V6M  [C_0603]  116.29 85.91 180 top
PC1111  22U_0603_6.3V6M  [C_0603]  116.73 79.15 270 top
PC1112  22U_0603_6.3V6M  [C_0603]  117.84 78.92 0 top
PC1113  22U_0603_6.3V6M  [C_0603]  116.51 80.18 90 top
PC1114  22U_0603_6.3V6M  [C_0603]  117.81 80.18 90 top
PC1115  22U_0603_6.3V6M  [C_0603]  116.51 83.99 270 top
PC1116  22U_0603_6.3V6M  [C_0603]  117.81 83.99 270 top
PC1117  22U_0603_6.3V6M  [C_0603]  118.94 82.63 0 top
PC1118  22U_0603_6.3V6M  [C_0603]  118.94 81.39 0 top
PC1119  22U_0603_6.3V6M  [C_0603]  118.94 80.14 0 top
PC1120  22U_0603_6.3V6M  [C_0603]  115.26 80.19 90 top
PC1121  22U_0603_6.3V6M  [C_0603]  115.51 79.15 270 top
PC1122  22U_0603_6.3V6M  [C_0603]  99.32 75.18 0 top
PC1123  22U_0603_6.3V6M  [C_0603]  99.32 75.18 0 bottom
PC1131  1U_0201_6.3V6M  [C_0201]  117.15 86.24 0 top
PC1132  1U_0201_6.3V6M  [C_0201]  117.15 85.63 0 top
PC1133  1U_0201_6.3V6M  [C_0201]  118.95 86.25 180 top
PC1134  1U_0201_6.3V6M  [C_0201]  118.95 85.64 180 top
PC1135  1U_0201_6.3V6M  [C_0201]  119.56 86.24 0 top
PC1136  1U_0201_6.3V6M  [C_0201]  119.56 85.64 0 top
PC1137  1U_0201_6.3V6M  [C_0201]  104.31 85.59 180 bottom
PC1138  1U_0201_6.3V6M  [C_0201]  114.31 84.03 90 top
PC1139  1U_0201_6.3V6M  [C_0201]  114.08 79.15 90 top
PC1140  1U_0201_6.3V6M  [C_0201]  114.33 80.72 90 top
PC1141  1U_0201_6.3V6M  [C_0201]  114.26 86.75 225 top
PC1142  330U_D3_2.5VY_R6M  [C_D3]  101.03 77.74 90 bottom
PC1143  330U_D3_2.5VY_R6M  [C_D3]  96.25 77.73 90 bottom
PC1146  100P_0201_25V8J  [C_0201]  118.52 77.97 0 top
PC1147  100P_0201_25V8J  [C_0201]  114.31 83.28 270 top
PC1148  27P_0201_25V8  [C_0201]  84.92 73.62 180 bottom
PC1149  82P_0201_50V8J  [C_0201]  84.92 74.66 180 bottom
PC1151  22U_0603_6.3V6M  [C_0603]  138.31 82.72 180 top
PC1152  22U_0603_6.3V6M  [C_0603]  137.93 83.92 180 top
PC1153  22U_0603_6.3V6M  [C_0603]  94.78 86.58 0 bottom
PC1154  22U_0603_6.3V6M  [C_0603]  92.81 86.58 180 bottom
PC1155  22U_0603_6.3V6M  [C_0603]  92.81 85.25 180 bottom
PC1156  22U_0603_6.3V6M  [C_0603]  92.81 85.26 180 top
PC1157  22U_0603_6.3V6M  [C_0603]  92.81 86.57 180 top
PC1158  22U_0603_6.3V6M  [C_0603]  94.78 86.59 0 top
PC1159  22U_0603_6.3V6M  [C_0603]  138.98 83.92 0 top
PC1160  22U_0603_6.3V6M  [C_0603]  139.47 79.41 0 top
PC1161  22U_0603_6.3V6M  [C_0603]  139.44 78.14 0 top
PC1166  100P_0201_25V8J  [C_0201]  139.86 86.18 0 top
PC1167  100P_0201_25V8J  [C_0201]  137.52 86.23 180 top
PC1168  27P_0201_25V8  [C_0201]  92.44 88.03 180 top
PC1169  82P_0201_50V8J  [C_0201]  92.44 87.47 180 top
PC1180  27P_0201_25V8  [C_0201]  120.99 101.24 180 bottom
PC1181  27P_0201_25V8  [C_0201]  120.99 100.65 180 bottom
PC3001  82P_0201_50V8J  [C_0201]  54.51 61.64 270 bottom
PC3002  0.01UF_0402_25V7K  [C_0402]  52.99 62.95 0 bottom
PC3003  82P_0201_50V8J  [C_0201]  49.9 56.71 180 bottom
PC3004  82P_0201_50V8J  [C_0201]  44.76 64.76 0 bottom
PC3005  0.22U_0402_10V6K  [C_0402]  47.33 63.3 180 bottom
PC3008  1U_0201_6.3V6M  [C_0201]  49.99 58.11 180 bottom
PC3009  1U_0201_6.3V6M  [C_0201]  49.99 58.68 180 bottom
PC3010  1U_0201_6.3V6M  [C_0201]  53.75 59.82 270 bottom
PC3011  1U_0201_6.3V6M  [C_0201]  54.34 59.83 270 bottom
PD1  CEST523NC5VB__SOT-523-3  [L03ESDL5V0CG3-2_SOT-523-3]  233.69 28.78 180 top
PD2  CEST523NC5VB__SOT-523-3  [L03ESDL5V0CG3-2_SOT-523-3]  235.85 28.78 180 top
PD3  BAS40CW_SOT323-3  [DB3J315E0L_SMINI3-F2-B3]  238.19 32.04 180 top
PD4  -  [L03ESDL5V0CG3-2_SOT-523-3]  45.1 96.94 180 top
PD5  S SCH DIO 5A 100V 15UA 0.88V TO227-3  [PDS5100H-13_POWERDI5-3]  49.06 87.31 0 bottom
PD700  30MA_30V_0.5UA_0.4V_SOD323-2  [SDMK0340L-7-F_SOD323-2]  41.61 62.29 180 top
PD701  -  [SMF4L22A_SOD123FL2]  56.94 83.75 90 bottom
PD702  30MA_30V_0.5UA_0.4V_SOD323-2  [SDMK0340L-7-F_SOD323-2]  41.47 60.56 180 top
PD704  -  [RB520SM-30T2R_EMD2-2]  41.69 58.86 180 top
PD705  -  [BAT54CW_SOT323-3]  46.81 67.83 0 top
PD800  -  [BAT54CW_SOT323-3]  40.45 81.92 0 top
PD801  S SCH DIO 5A 100V 15UA 0.88V TO227-3  [PDS5100H-13_POWERDI5-3]  48.58 82.18 180 bottom
PD802  30MA_30V_0.5UA_0.4V_SOD323-2  [SDMK0340L-7-F_SOD323-2]  47.44 82.45 180 top
PD803  -  [BAT54CW_SOT323-3]  60.93 94.47 180 bottom
PD901  -  [L03ESDL5V0CG3-2_SOT-523-3]  41.05 41.32 0 top
PD902  -  [L03ESDL5V0CG3-2_SOT-523-3]  38.63 41.32 0 top
PD3000  -  [BAT54CW_SOT323-3]  43.57 68 270 bottom
PD3001  -  [RB520SM-30T2R_EMD2-2]  49.94 59.76 0 bottom
PD3002  -  [RB520SM-30T2R_EMD2-2]  48.34 62.56 90 bottom
PH601  470K_0402_5%_B25/50 4700K  [R_0402]  73.32 93.89 0 bottom
PH602  10K_0402_5%_B25/50 4250K  [R_0402]  82.32 85.29 90 bottom
PH603  470K_0402_5%_B25/50 4700K  [R_0402]  77.26 66.26 0 bottom
PH604  10KB_0402_5%  [R_0402]  90.54 87.02 90 bottom
PH605  10K_0402_5%_B25/50 4250K  [R_0402]  89.46 66.72 180 bottom
PJP1  PAD-OPEN1x1m  [JUMP_43X39]  146.84 106.41 0 top
PJP2  PAD-OPEN1x1m  [JUMP_43X39]  140.72 105.9 90 top
PJP3  PAD-OPEN1x3m  [JUMP_43X118]  167.52 98.08 270 top
PJP5  -  [JUMP_43X79]  20.9 91.52 90 top
PJP6  PAD-OPEN1x1m  [JUMP_43X39]  23.95 93.22 270 top
PJP8  PAD-OPEN1x2m  [JUMP_43X79]  36.28 63.42 180 top
PJP12  PAD-OPEN1x1m  [JUMP_43X39]  104.65 101.8 270 bottom
PJP14  PAD-OPEN1x2m  [JUMP_43X79]  289.2 59.91 0 top
PJP15  PAD-OPEN1x1m  [JUMP_43X39]  289.6 54.52 0 top
PJP16  PAD-OPEN1x1m  [JUMP_43X39]  298.69 52.58 0 top
PJP17  PAD-OPEN1x2m  [JUMP_43X79]  290.12 51.49 180 top
PJP18  PAD-OPEN1x1m  [JUMP_43X39]  298.69 50.32 0 top
PJP19  PAD-OPEN1x1m  [JUMP_43X39]  291.79 33.92 270 top
PJP20  PAD-OPEN1x1m  [JUMP_43X39]  286.23 80.94 180 top
PJP22  PAD-OPEN1x1m  [JUMP_43X39]  276.49 71.61 90 top
PJP31  PAD-OPEN1x3m  [JUMP_43X118]  21.68 29.04 270 top
PJP35  PAD-OPEN1x1m  [JUMP_43X39]  247.2 34.28 0 top
PJP36  PAD-OPEN1x2m  [JUMP_43X79]  262.26 39.15 270 top
PJP38  PAD-OPEN1x1m  [JUMP_43X39]  179.22 91.54 270 top
PJP39  PAD-OPEN1x3m  [JUMP_43X118]  176.85 99.01 90 top
PJP40  PAD-OPEN1x2m  [JUMP_43X79]  270.92 39.43 0 top
PJP41  PAD-OPEN1x3m  [JUMP_43X118]  263.98 60.34 90 top
PJP42  PAD-OPEN1x1m  [JUMP_43X39]  292.17 23.85 180 top
PJP100  PAD-OPEN 1x2m~D  [JUMP_43X79]  190.16 101.86 270 bottom
PJP101  PAD-OPEN 1x2m~D  [JUMP_43X79]  50.87 31.43 270 bottom
PJP102  -  [JUMP_43X118]  187.01 87.31 180 bottom
PJP103  -  [JUMP_43X118]  36.74 27.13 90 top
PJP200  -  [JUMP_43X118]  205.47 34.61 90 top
PJP201  -  [JUMP_43X39]  225.04 32.82 0 top
PJP202  PAD-OPEN 1x2m~D  [JUMP_43X79]  216.44 33.29 270 bottom
PJP301  PAD-OPEN 1x2m~D  [JUMP_43X79]  184.87 106.58 0 top
PJP302  -  [JUMP_43X118]  172.07 109.09 180 bottom
PJP401  -  [JUMP_43X79]  76.61 26.84 90 top
PJP402  -  [JUMP_43X79]  191.48 27.68 0 top
PJP403  PAD-OPEN1x1m  [JUMP_43X39]  92.46 28.9 180 top
PJP404  PAD-OPEN1x1m  [JUMP_43X39]  175.19 27.87 0 top
PJP501  PAD-OPEN1x1m  [JUMP_43X39]  184.97 103.64 90 bottom
PJP502  PAD-OPEN1x1m  [JUMP_43X39]  173.11 103.83 180 bottom
PJP505  PAD-OPEN1x1m  [JUMP_43X39]  125.02 28.43 180 top
PJP506  PAD-OPEN1x1m  [JUMP_43X39]  117.68 28.38 180 top
PJP601  PAD-OPEN 4x4m  [JUMP_43X118]  64.71 86.76 270 bottom
PJP602  PAD-OPEN 1x2m~D  [JUMP_43X79]  72.97 80.22 90 top
PJP603  PAD-OPEN1x1m  [JUMP_43X39]  98 99.38 180 bottom
PJP700  PAD-OPEN 4x4m  [JUMP_43X118-NPM]  54.89 79.24 270 bottom
PJPDC1  CVILU_CI0805M1HRC-NH  [CVILU_CI0805M1HRC-NH_5P-T]  45.53 98.8 270 bottom
PL1  FBMJ4516HS720NT_2P  [TAIYO_FBMJ4516HS720NT_2P]  235.95 38 90 bottom
PL2  FBMJ4516HS720NT_2P  [TAIYO_FBMJ4516HS720NT_2P]  238.25 38 90 bottom
PL3  BLM15AG102SN1D_2P  [MURAT_BLM15AG102SN1D_2P]  45.55 99.4 180 top
PL4  FBMJ4516HS720NT_2P  [TAIYO_FBMJ4516HS720NT_2P]  48.32 94.67 0 bottom
PL100  1.5UH_9A_20%_7X7X3_M  [L_7X7X3_M_2P]  196.16 96.11 225 bottom
PL101  1.5UH_9A_20%_7X7X3_M  [L_7X7X3_M_2P]  45.05 18.98 180 bottom
PL201  1UH_PCMB063T-1R0MS_12A_20%  [CYNTE_PCMB063T-1R0MS_2P]  213.92 28.61 180 bottom
PL301  0.68UH_7.9A_20%_5X5X3_M  [L_5X5X3_M_2P]  185.4 110.14 180 bottom
PL402  1UH_1277AS-H-1R0N-P2_3.3A_30%  [MAG_MLV-FY12N1R0M-O1L_2P]  81.81 26.45 180 top
PL404  1UH_1277AS-H-1R0N-P2_3.3A_30%  [MAG_MLV-FY12N1R0M-O1L_2P]  186.86 27.22 0 top
PL405  3A_Z120_40M_0603_2P  [3A_Z120_0603_2P]  92.62 27.06 180 top
PL406  3A_Z120_40M_0603_2P  [3A_Z120_0603_2P]  175 25.97 0 top
PL501  1UH_1277AS-H-1R0N-P2_3.3A_30%  [MAG_MLV-FY12N1R0M-O1L_2P]  176.57 105.42 270 bottom
PL502  3A_Z120_40M_0603_2P  [3A_Z120_0603_2P]  183.13 103.81 90 bottom
PL602  9A Z80 10M 1812_2P  [9A_Z80_1812_2P-NPM]  64.74 88.11 270 bottom
PL610  0.15UH_MMD-06CZER15MEX5L__35A_20%  [L_7X7X3_M]  85.24 87.29 90 bottom
PL612  0.15UH_MMD-06CZER15MEX5L__35A_20%  [L_7X7X3_M]  87.44 69.59 180 bottom
PL613  0.15UH_MMD-06CZER15MEX5L__35A_20%  [L_7X7X3_M]  90.92 78.69 180 bottom
PL614  0.47UH_NA_12.2A_20%  [MAG_MMD05CZR47M_4P]  93.04 89.06 90 bottom
PL700  1UH_PCMB051H-1R0MS_8A_20%  [CYNTE_PCMB051H-1R0MS_2P]  54.89 80.87 270 bottom
PL701  2.2UH_PCMB103T-2R2MS_13A_20%  [CYNTE_PCMB103T-2R2MS_2P]  57.97 70.97 0 bottom
PL800  5A_Z80_20M_0805_2P  [TAI-T_HCB2012KF-121T50_2P]  42.45 86.32 270 bottom
PL801  5A_Z80_20M_0805_2P  [TAI-T_HCB2012KF-121T50_2P]  40.61 86.32 270 bottom
PL901  FBMJ4516HS720NT_2P  [TAIYO_FBMJ4516HS720NT_2P]  44.58 45.69 0 bottom
PL902  FBMJ4516HS720NT_2P  [TAIYO_FBMJ4516HS720NT_2P]  44.58 43.43 0 bottom
PQ1  L2N7002DW1T1G_SC88-6  [DMN65D8LDW-7_SOT363-6]  68.39 92.94 180 top
PQ2  -  [FDV301N-G_SOT23-3]  52.51 84.44 270 top
PQ3  LMBT3904WT1G_SC70-3  [MMST3904-7-F_SOT323-3]  53.61 81.26 90 top
PQ4  EMZB08P03V_EDFN3X3-8-5  [FDMC6679AZ_MLP8-5]  51.47 90.66 90 bottom
PQ5  AO3409 P-CHANNEL SOT-23  [AO3409_SOT23-3]  74.5 96.02 270 top
PQ6  L2N7002WT1G_SC-70-3  [DMN65D8LW-7_SOT323-3]  63.64 88.2 180 top
PQ7  L2N7002WT1G_SC-70-3  [DMN65D8LW-7_SOT323-3]  80.19 95.18 180 top
PQ8  L2N7002WT1G_SC-70-3  [DMN65D8LW-7_SOT323-3]  53.84 96.09 270 top
PQ9  EMZB08P03VL_P_DFN33-8-5  [FDMC6679AZ_MLP8-5]  57.06 91.08 0 bottom
PQ10  L2N7002DW1T1G_SC88-6  [DMN65D8LDW-7_SOT363-6]  53.57 88.53 0 top
PQ11  AO3409 P-CHANNEL SOT-23  [AO3409_SOT23-3]  60.49 89.34 90 top
PQ12  L2N7002WT1G_SC-70-3  [DMN65D8LW-7_SOT323-3]  57.49 93 180 top
PQ13  L2N7002WT1G_SC-70-3  [DMN65D8LW-7_SOT323-3]  236.62 36.77 90 top
PQ614  AONH36334 _DFN3X3A8-10  [AON7934_DFN3X3A8-10]  96.59 97.42 0 bottom
PQ700  AOE6936_DFN5X6E8-10  [AOE6930_DFN5X6E8-10]  49.08 66.64 90 bottom
PQ701  AOE6936_DFN5X6E8-10  [AOE6930_DFN5X6E8-10]  61.45 82.46 0 bottom
PQ702  EMZB08P03V_EDFN3X3-8-5  [FDMC6679AZ_MLP8-5]  230.25 39.71 90 bottom
PQ703  L2N7002WT1G_SC-70-3  [DMN65D8LW-7_SOT323-3]  41.59 66.79 180 top
PQ800  EMZB08P03VL_P_DFN33-8-5  [FDMC6679AZ_MLP8-5]  40.78 83.47 0 bottom
PQ801  EMZB08P03V_EDFN3X3-8-5  [FDMC6679AZ_MLP8-5]  47.03 78.49 270 bottom
PQ802  L2N7002DW1T1G_SC88-6  [DMN65D8LDW-7_SOT363-6]  43.42 99.41 180 top
PQ803  AO3409 P-CHANNEL SOT-23  [AO3409_SOT23-3]  39.31 88.49 180 top
PQ804  L2N7002DW1T1G_SC88-6  [DMN65D8LDW-7_SOT363-6]  36.63 97.38 180 top
PQ805  AO3409 P-CHANNEL SOT-23  [AO3409_SOT23-3]  33.76 90.01 270 top
PQ806  L2N7002DW1T1G_SC88-6  [DMN65D8LDW-7_SOT363-6]  46.78 96.22 0 top
PQ807  L2N7002WT1G_SC-70-3  [DMN65D8LW-7_SOT323-3]  39.83 101.29 90 top
PQ808  L2N7002DW1T1G 2N SC88-6  [DMN66D0LDW-7_SOT363-6]  38.28 103.96 180 top
PQ809  L2N7002DW1T1G 2N SC88-6  [DMN66D0LDW-7_SOT363-6]  44.6 107.72 180 top
PQ810  L2N7002DW1T1G 2N SC88-6  [DMN66D0LDW-7_SOT363-6]  35.85 102.51 90 top
PQ811  L2N7002DW1T1G 2N SC88-6  [DMN66D0LDW-7_SOT363-6]  52.54 103.14 0 top
PQ812  L2N7002WT1G_SC-70-3  [DMN65D8LW-7_SOT323-3]  55.18 105.02 90 top
PQ813  L2N7002DW1T1G_SC88-6  [DMN65D8LDW-7_SOT363-6]  45.72 85.86 180 top
PQ814  L2N7002WT1G_SC-70-3  [DMN65D8LW-7_SOT323-3]  39.97 97.04 0 top
PQ3000  L2N7002DW1T1G 2N SC88-6  [DMN65D8LDW-7_SOT363-6]  52.86 58.51 270 bottom
PR1  100K_0402_5%  [R_0402]  233.31 32.14 270 top
PR2  1K_0402_5%  [R_0402]  239.46 34.96 180 top
PR3  0_0402_5%  [R_0402]  52.62 86.85 0 top
PR4  2.2K_0402_5%  [R_0402]  50.18 90.85 90 top
PR5  33_0402_5%  [R_0402]  53.55 87.62 180 top
PR6  100K_0402_1%  [R_0402]  50.58 83.06 270 top
PR7  10K_0402_1%  [R_0402]  55.56 81.18 180 top
PR8  15K_0402_1%  [R_0402]  50.58 81.34 270 top
PR9  10M_0402_5%  [R_0402]  239.63 36.52 90 top
PR10  300K_0402_5%  [R_0402]  69.79 93.61 270 top
PR11  499K_0402_1%  [R_0402]  49.47 91.93 90 bottom
PR12  1M_0402_5%  [R_0402]  58.31 92.97 0 bottom
PR13  4.7K_0805_5%  [R_0805]  57.13 86.23 0 top
PR14  100K_0402_5%  [R_0402]  56.95 84.83 0 top
PR15  100K_0402_5%  [R_0402]  69.79 91.95 270 top
PR16  49.9K_0402_1%  [R_0402]  78.43 95.96 270 top
PR17  100K_0402_5%  [R_0402]  65.09 93.47 270 top
PR18  1M_0402_5%  [R_0402]  61.27 87.88 0 top
PR19  0_0402_5%  [R0402_0OHM]  65.92 91.8 90 top
PR20  0_0402_5%  [R0402_0OHM]  81.36 98.19 180 top
PR22  0_0402_5%  [R0402_0OHM]  63.4 92.63 0 top
PR24  100K_0402_5%  [R_0402]  79.71 98.19 180 top
PR25  0_0402_5%  [R0402_0OHM]  65.93 90.15 90 top
PR27  100K_0402_5%  [R_0402]  63.4 93.44 0 top
PR28  100K_0402_5%  [R_0402]  50.74 94.85 90 top
PR31  1M_0402_5%  [R_0402]  55.95 87.17 90 top
PR32  1M_0402_5%  [R_0402]  56.58 88.88 90 top
PR33  100K_0402_5%  [R_0402]  54.35 91.35 180 top
PR38  100_0402_5%  [R_0402]  235.91 32.14 270 top
PR39  100_0402_5%  [R_0402]  235.02 32.14 270 top
PR40  100_0402_5%  [R_0402]  234.13 32.14 270 top
PR41  0_0402_5%  [R0402_0OHM]  54.56 92.17 0 top
PR42  0_0402_5%  [R0402_0OHM]  52.38 91.68 180 top
PR43  0_0402_5%  [R_0402]  55.47 92.98 180 top
PR44  0_0402_5%  [R0402_0OHM]  53.55 98.74 180 top
PR45  10K_0402_5%  [R_0402]  54.55 93.82 0 top
PR46  0_0402_5%  [R0402_0OHM]  57.07 91.74 0 top
PR47  0_0402_5%  [R0402_0OHM]  55.8 96.53 270 top
PR49  0_0402_5%  [R0402_0OHM]  58.74 96.45 180 top
PR100  0_0603_5%  [R0603_0OHM]  191.84 100.47 0 top
PR102  499K_0402_1%  [R_0402]  185.59 94.77 0 bottom
PR103  499K_0402_1%  [R_0402]  186.51 93.88 270 bottom
PR104  0_0402_5%  [R0402_0OHM]  193.49 95.03 0 top
PR105  0_0402_5%  [R0402_0OHM]  193.49 94.24 0 top
PR106  4.7_1206_5%  [R_1206]  196.99 94.33 225 top
PR107  100K_0402_5%  [R_0402]  186.55 95.94 0 top
PR108  1K_0402_5%  [R_0402]  191.59 93.64 180 top
PR111  0_0603_5%  [R0603_0OHM]  43.14 25.32 270 top
PR112  4.7_1206_5%  [R_1206]  44.75 16.74 90 top
PR113  100K_0402_5%  [R_0402]  46.78 32.63 90 top
PR114  0_0402_5%  [R_0402]  185.59 94.8 0 top
PR116  1M_0402_1%  [R_0402]  189.81 94.56 270 top
PR117  1K_0402_5%  [R_0402]  44.42 33.26 180 top
PR119  0_0402_5%  [R0402_0OHM]  187.47 96.74 180 top
PR120  0_0402_5%  [R0402_0OHM]  185.17 95.8 90 bottom
PR202  4.7_1206_5%  [R_1206]  214.83 35.74 180 top
PR203  0_0603_5%  [R0603_0OHM]  218.7 31.74 180 top
PR204  102K_0402_1%  [R_0402]  216.15 28.82 0 top
PR205  0_0402_5%  [R_0402]  216.72 26.6 0 top
PR206  100K_0402_1%  [R_0402]  217.87 28.11 90 top
PR207  0_0402_5%  [R_0402]  217.63 25.84 180 top
PR208  0_0402_5%  [R0402_0OHM]  227.16 24.31 180 top
PR209  1M_0402_5%  [R_0402]  225.43 24.3 180 top
PR210  0_0402_5%  [R0402_0OHM]  227.16 25.08 180 top
PR212  1M_0402_5%  [R_0402]  226.24 25.9 0 top
PR302  1M_0402_1%  [R_0402]  194.82 104.97 270 bottom
PR303  4.7_1206_5%  [R_1206]  188.4 112.13 0 top
PR304  0_0603_5%  [R0603_0OHM]  189.39 109.19 180 top
PR306  22.1K_0402_1%  [R_0402]  195.28 109.63 270 top
PR307  0_0402_5%  [R_0402]  196.3 106.09 180 top
PR308  1K_0402_5%  [R_0402]  196.1 109.62 270 top
PR310  0_0402_5%  [R_0402]  195.39 105.2 0 top
PR311  29.4K_0402_1%  [R_0402]  195.39 106.98 0 top
PR312  22K_0402_1%  [R_0402]  195.65 104.06 90 bottom
PR313  100K_0402_5%  [R_0402]  194.29 107.69 0 bottom
PR314  0_0402_5%  [R0402_0OHM]  194.29 108.5 0 bottom
PR315  0_0402_5%  [R0402_0OHM]  194.81 30.65 0 top
PR402  0_0402_5%  [R0402_0OHM]  80.02 31.88 270 top
PR403  1M_0402_1%  [R_0402]  80.84 30.97 90 top
PR404  0_0402_5%  [R_0402]  80.02 29.25 90 top
PR405  4.7_0603_5%  [R_0603]  80.75 24.38 180 top
PR406  22K_0402_1%  [R_0402]  176.26 23.77 90 top
PR407  1M_0402_1%  [R_0402]  175.46 24.69 270 top
PR408  0_0402_5%  [R_0402]  179.95 28.51 0 top
PR409  4.7_0603_5%  [R_0603]  187.05 25.27 270 top
PR410  10K_0402_1%  [R_0402]  178.55 23.79 90 top
PR411  0_0402_5%  [R_0402]  185.76 32.05 270 top
PR412  0_0402_5%  [R_0402]  84.26 24.37 0 top
PR413  10K_0402_1%  [R_0402]  88.66 25.25 180 top
PR414  10K_0402_1%  [R_0402]  89.91 25.25 0 top
PR415  10K_0402_1%  [R_0402]  87.75 24.49 0 top
PR416  10K_0402_1%  [R_0402]  90.82 24.49 180 top
PR417  10K_0402_1%  [R_0402]  184.15 32.05 270 top
PR418  10K_0402_1%  [R_0402]  183.33 31.88 270 top
PR419  10K_0402_1%  [R_0402]  184.97 31.13 90 top
PR420  10K_0402_1%  [R_0402]  182.51 31.25 270 top
PR421  0_0402_5%  [R_0402]  82.65 23.71 90 top
PR422  0_0402_5%  [R_0402]  83.49 24.63 270 top
PR423  0_0402_5%  [R0402_0OHM]  186.68 29.25 0 top
PR424  100K_0402_1%  [R_0402]  186.68 30.08 0 top
PR425  0_0402_5%  [R_0402]  78.23 31.25 270 top
PR427  0_0402_5%  [R0402_0OHM]  85.94 24.51 0 top
PR428  1M_0402_1%  [R_0402]  186.68 30.91 0 top
PR429  0_0402_5%  [R0402_0OHM]  79.03 31.25 270 top
PR430  0_0402_5%  [R_0402]  179.39 23.79 90 top
PR501  20K_0402_1%  [R_0402]  180.97 102.24 90 bottom
PR502  4.7_0603_5%  [R_0603]  177.47 106.75 180 bottom
